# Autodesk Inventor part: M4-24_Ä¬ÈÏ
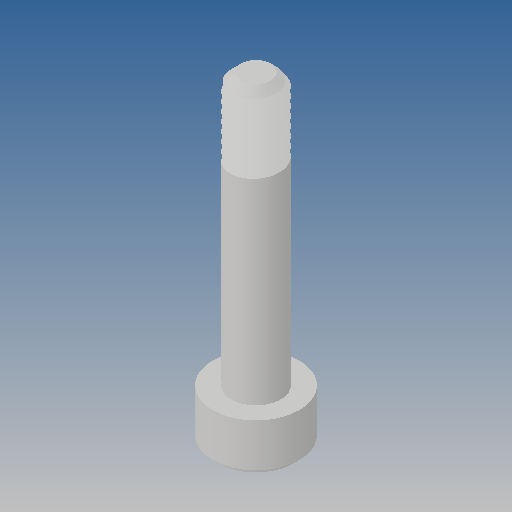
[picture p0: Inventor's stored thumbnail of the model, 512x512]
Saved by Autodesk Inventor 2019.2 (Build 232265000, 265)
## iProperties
Created: 2010-06
Part Number: M4-24_Ä¬ÈÏ
Material: Ogólny
Document SubType Name: Modeling
Designer: CADENGINEERING4
Density: 1 g/cm^3
Appearance: Domyślna
Author: CADENGINEERING4
Revision Number: ÈÎºÎ
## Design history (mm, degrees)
feature "NONE"
node "Bryła1"
